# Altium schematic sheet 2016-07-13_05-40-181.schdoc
size 313 x 127 mm; SheetNumber: 1; SheetTotal: 1
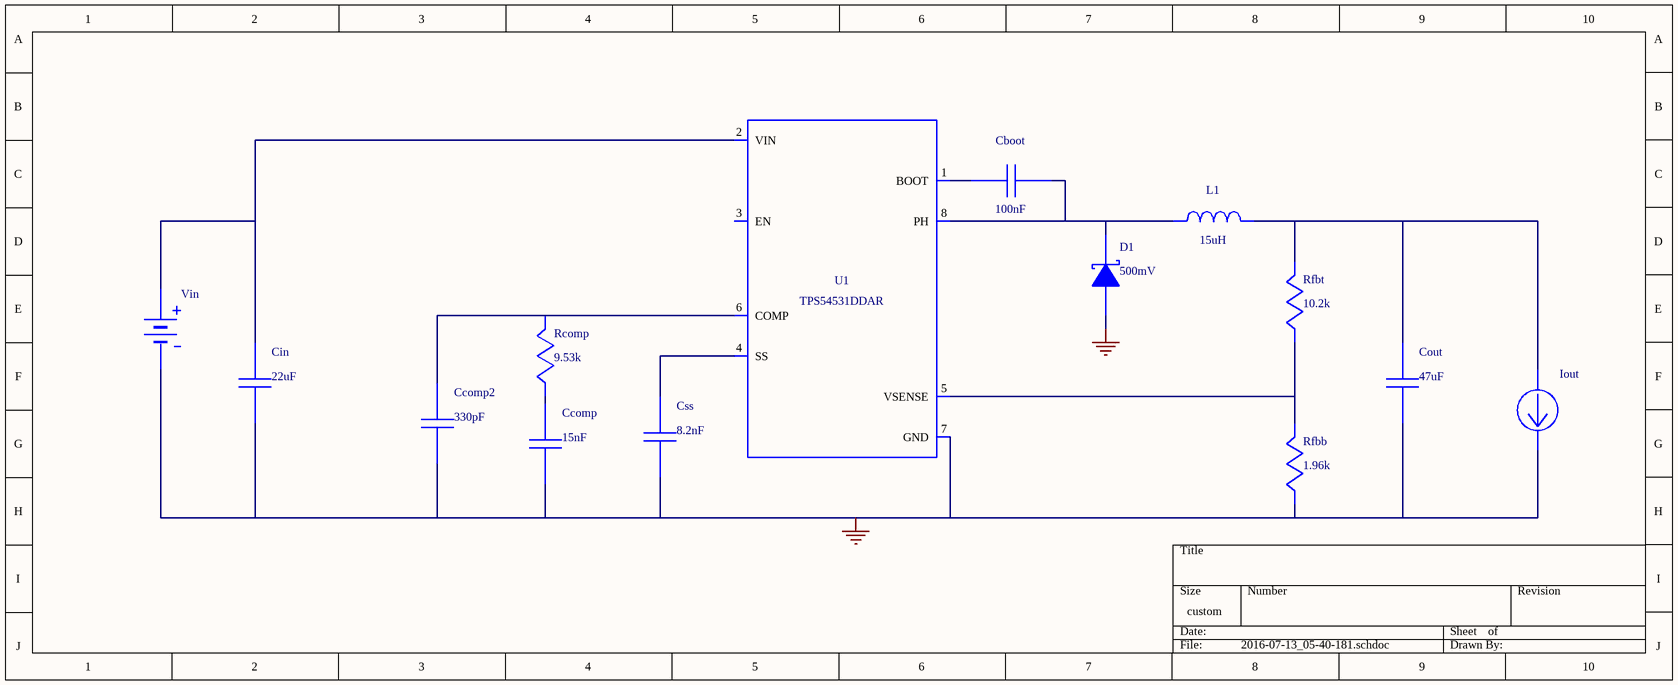
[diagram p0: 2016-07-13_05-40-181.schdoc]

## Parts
Cboot  value 100nF  (hidden comment: GRM155R61A104KA01D)
Ccomp  value 15nF  (hidden comment: CC0805KRX7R9BB153)
Ccomp2  value 330pF  (hidden comment: CL21C331JBANFNC)
Cin  value 22uF  (hidden comment: GRM32ER61E226KE15L)
Cout  value 47uF  (hidden comment: GRM31CR61A476KE15L)
Css  value 8.2nF  (hidden comment: GRM033R61A822KA01D)
D1  value 500mV  (hidden comment: B220-13-F)
Iout  WB_CURRENT_LOAD  (value not drawn)
L1  value 15uH  (hidden comment: SRN8040-150M)
Rcomp  value 9.53k  (hidden comment: CRCW04029K53FKED)
Rfbb  value 1.96k  (hidden comment: CRCW04021K96FKED)
Rfbt  value 10.2k  (hidden comment: CRCW040210K2FKED)
U1  TPS54531DDAR
Vin  WB_BATTERY  (value not drawn)

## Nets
0: Ccomp.2 Ccomp2.2 Cin.2 Cout.2 Css.2 D1.2(A) Iout.2(-) Rfbb.2 U1.7(GND) U1.9(ETPAD) Vin.2(-)
NetCboot_1: Cboot.1 U1.1(BOOT)
NetCboot_2: Cboot.2 D1.1(K) L1.2 U1.8(PH)
NetCcomp2_1: Ccomp2.1 Rcomp.1 U1.6(COMP)
NetCcomp_1: Ccomp.1 Rcomp.2
NetCin_1: Cin.1 U1.2(VIN) Vin.1(+)
NetCout_1: Cout.1 Iout.1(+) L1.1 Rfbt.1
NetCss_1: Css.1 U1.4(SS)
NetRfbb_1: Rfbb.1 Rfbt.2 U1.5(VSENSE)

Not connected (* = marked no-connect by the designer): U1 3(EN)

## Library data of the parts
Cboot = GRM155R61A104KA01D: GRM155R61A104KA0; Manufacturer Name: MuRata
Ccomp = CC0805KRX7R9BB153: CC0805KRX7R9BB15; Manufacturer Name: Yageo America
Ccomp2 = CL21C331JBANFNC: Manufacturer Name: Samsung Electro-Mechanics
Cin = GRM32ER61E226KE15L: GRM32ER61E226KE1; Manufacturer Name: MuRata
Cout = GRM31CR61A476KE15L: GRM31CR61A476KE1; Manufacturer Name: MuRata
Css = GRM033R61A822KA01D: GRM033R61A822KA0; Manufacturer Name: MuRata
D1 = B220-13-F: Manufacturer Name: Diodes Inc.
L1 = SRN8040-150M: Manufacturer Name: Bourns
Rcomp = CRCW04029K53FKED: Manufacturer Name: Vishay-Dale
Rfbb = CRCW04021K96FKED: Manufacturer Name: Vishay-Dale
Rfbt = CRCW040210K2FKED: Manufacturer Name: Vishay-Dale
U1 = TPS54531DDAR: Manufacturer Name: Texas Instruments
